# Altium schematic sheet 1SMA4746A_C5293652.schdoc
size 127 x 101 mm
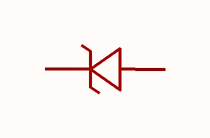
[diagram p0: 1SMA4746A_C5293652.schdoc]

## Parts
U?  1sma4746a_c5293652  [SMA_L4.3-W2.6-LS5.0-RD]  (value not drawn)

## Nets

Not connected (* = marked no-connect by the designer): U? 1(K) 2(A)

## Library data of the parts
U? = 1sma4746a_c5293652: 稳压值(标称值):18V;稳压值(范围):-;耗散功率(Pd):1W;; Manufacturer: CJ(江苏长电/长晶); AddInBom: yes; ModelId: 8d2dd2e50a3a4b27821fa63d469a8f11; ModelTransform: 196.85,102.362,0,0,0,0,0,0,0; Zener Voltage(Nom): 18V; Reverse Leakage Current (Ir): 100nA; Pd - Power Dissipation: 1W; Impedance(Zzt): 20Ω; Impedance(Zzk): 750Ω; Operating Junction Temperature Range: -55℃~+150℃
